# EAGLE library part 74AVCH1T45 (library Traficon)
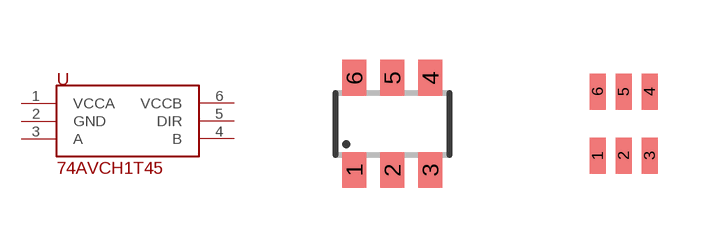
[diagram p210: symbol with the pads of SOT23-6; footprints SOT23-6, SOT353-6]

Designator prefix U

## 74AVCH1T45DBV  [SOT23-6]
1  VCCA  sup
2  GND  sup
3  A
4  B
5  DIR  in
6  VCCB  sup

## 74AVCH1T45DCK  [SOT353-6]
Pads as for SOT23-6

## Footprint SOT23-6 (pad centres in mm)
Small Outline Transistor 6 lead
smd 0.6 x 0.9: 1 -0.95,-1.15; 2 0,-1.15; 3 0.95,-1.15; 4 0.95,1.15; 5 0,1.15; 6 -0.95,1.15

## Footprint SOT353-6 (pad centres in mm)
smd 0.4 x 0.9: 1 -0.65,-0.8; 2 0,-0.8; 3 0.65,-0.8; 4 0.65,0.8; 5 0,0.8; 6 -0.65,0.8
